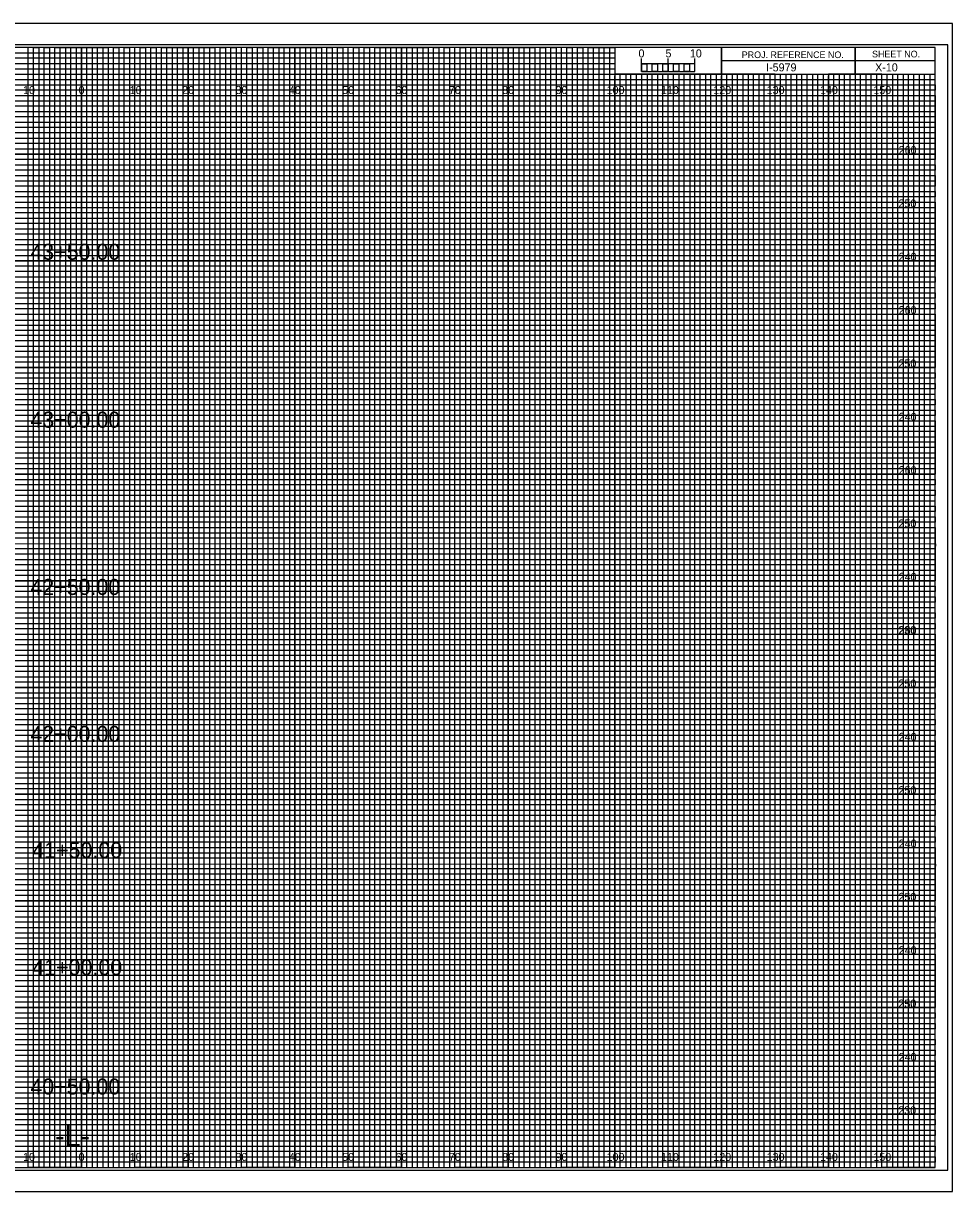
# Model space of a CAD drawing. Extents: x -13 to 359, y -5 to 2854.
# Drawn here: x 149.1 to 323.3, y 1975.5 to 2194.5 of the extents above; entities that cross this region are included whole.
import ezdxf

# ---------------------------------------------------------------- set-up
doc = ezdxf.new("R2010")
doc.units = 0
for name, color, linetype in [('Exist CMT Pavement', 7, 'Continuous'), ('Exist Cross Section Cell', 7, 'Continuous'), ('Exist XS Ground Line', 7, 'Continuous'), ('Prop CMT Conc Surface', 7, 'Continuous'), ('Prop CMT Concrete Structures', 7, 'Continuous'), ('Prop CMT DNC', 7, 'Continuous'), ('Prop CMT Pvmt Course 1', 7, 'Continuous'), ('Prop CMT Pvmt Course 1 CG', 7, 'Continuous'), ('Prop CMT Pvmt Course 1 Wedge', 7, 'Continuous'), ('Prop CMT Pvmt Course 2', 7, 'Continuous'), ('Prop CMT Pvmt Course 2 Wedge', 7, 'Continuous'), ('Prop CMT Pvmt Course 3', 7, 'Continuous'), ('Prop CMT Pvmt Course 3 Wedge', 7, 'Continuous'), ('Prop CMT Shear Line', 7, 'Continuous'), ('Prop CMT Slope Grass', 7, 'Continuous'), ('Prop CMT Subgrade Earthwork', 7, 'Continuous'), ('Scratch_Level_0', 7, 'Continuous')]:
    doc.layers.add(name, color=color, linetype=linetype)

msp = doc.modelspace()

# ---------------------------------------------------------------- linework, layer by layer
at = {"layer": 'Exist XS Ground Line'}
for p, q in [((150, 2190), (140, 2190)), ((150, 1980), (150, 2190)), ((170, 2190), (160, 2190)), ((160, 2190), (160, 1980)), ((170, 1980), (170, 2190)), ((190, 2190), (180, 2190)), ((180, 2190), (180, 1980)), ((190, 1980), (190, 2190)), ((210, 2190), (200, 2190)), ((200, 2190), (200, 1980)), ((210, 1980), (210, 2190)), ((230, 2190), (220, 2190)), ((220, 2190), (220, 1980)), ((230, 1980), (230, 2190)), ((250, 2190), (240, 2190)), ((240, 2190), (240, 1980)), ((250, 1980), (250, 2190)), ((260, 2190), (260, 1980)), ((270, 1980), (270, 2185)), ((290, 2185), (280, 2185)), ((280, 2185), (280, 1980)), ((290, 1980), (290, 2185)), ((310, 2185), (300, 2185)), ((300, 2185), (300, 1980)), ((310, 1980), (310, 2185)), ((160, 1980), (150, 1980)), ((180, 1980), (170, 1980)), ((200, 1980), (190, 1980)), ((220, 1980), (210, 1980)), ((240, 1980), (230, 1980)), ((260, 1980), (250, 1980)), ((280, 1980), (270, 1980)), ((300, 1980), (290, 1980)), ((320, 1980), (310, 1980)), ((320, 1980), (320, 1980))]:
    msp.add_line(p, q, dxfattribs=at)
for points in [[(0, 2180), (320, 2180), (320, 2170), (0, 2170)], [(0, 2160), (320, 2160), (320, 2150), (0, 2150)], [(0, 2140), (320, 2140), (320, 2130), (0, 2130)], [(0, 2120), (320, 2120), (320, 2110), (0, 2110)], [(0, 2100), (320, 2100), (320, 2090), (0, 2090)], [(0, 2080), (320, 2080), (320, 2070), (0, 2070)], [(0, 2060), (320, 2060), (320, 2050), (0, 2050)], [(0, 2040), (320, 2040), (320, 2030), (0, 2030)], [(0, 2020), (320, 2020), (320, 2010), (0, 2010)], [(0, 2000), (320, 2000), (320, 1990), (0, 1990)]]:
    msp.add_lwpolyline(points, dxfattribs=at)
at = {"layer": 'Prop CMT Conc Surface'}
for p, q in [((265, 2185.49), (265, 2187.9)), ((265, 2186.9), (265, 2187.9)), ((270, 2185.49), (270, 2187.9)), ((275, 2185.49), (275, 2187.9)), ((275, 2186.9), (275, 2187.9))]:
    msp.add_line(p, q, dxfattribs=at)
for points in [[(275, 2186.9), (265, 2186.9), (265, 2185.49), (275, 2185.49)], [(265, 2186.9), (266, 2186.9), (266, 2185.49), (265, 2185.49)], [(267, 2186.9), (268, 2186.9), (268, 2185.49), (267, 2185.49)], [(269, 2186.9), (270, 2186.9), (270, 2185.49), (269, 2185.49)], [(271, 2186.9), (272, 2186.9), (272, 2185.49), (271, 2185.49)], [(273, 2186.9), (274, 2186.9), (274, 2185.49), (273, 2185.49)]]:
    msp.add_lwpolyline(points, close=True, dxfattribs=at)
at = {"layer": 'Prop CMT Concrete Structures'}
for p, q in [((305, 2190), (305, 2185)), ((305, 2185), (305, 2190)), ((280, 2187.5), (280, 2185)), ((320, 2187.49), (280, 2187.49)), ((280, 2185), (320, 2185))]:
    msp.add_line(p, q, dxfattribs=at)
for points in [[(320, 2190), (0, 2190), (0, 1980), (320, 1980)], [(280, 2190), (260, 2190), (260, 2185.03), (280, 2185.03)], [(320, 2190), (280, 2190), (280, 2185), (320, 2185)]]:
    msp.add_lwpolyline(points, close=True, dxfattribs=at)
at = {"layer": 'Prop CMT DNC'}
for p, q in [((323.3, 2194.5), (-13.4, 2194.5)), ((-13.4, 1975.5), (323.3, 1975.5))]:
    msp.add_line(p, q, dxfattribs=at)
at = {"layer": 'Prop CMT Pvmt Course 1'}
for p, q in [((0, 2189), (260, 2189)), ((260, 2187.98), (0, 2187.98)), ((260, 2189), (260, 2187.98)), ((0, 2187), (260, 2187)), ((260, 2185.89), (0, 2185.89)), ((260, 2187), (260, 2185.89)), ((0, 2184), (320, 2184))]:
    msp.add_line(p, q, dxfattribs=at)
for points in [[(0, 2183), (270, 2183), (320, 2183), (320, 2182), (0, 2182)], [(0, 2181), (320, 2181), (320, 2179), (0, 2179)], [(0, 2178), (320, 2178), (320, 2177), (0, 2176.98)], [(0, 2176), (320, 2176), (320, 2174), (0, 2174)], [(0, 2173), (320, 2173), (320, 2172), (0, 2172)], [(0, 2171), (320, 2171), (320, 2169), (0, 2169)], [(0, 2168), (320, 2168), (320, 2167), (0, 2167)], [(0, 2166), (320, 2166), (320, 2164), (0, 2164)], [(0, 2163), (320, 2163), (320, 2162), (0, 2162)], [(0, 2161), (320, 2161), (320, 2159), (0, 2159)], [(0, 2158), (320, 2158), (320, 2157), (0, 2157)], [(0, 2156), (320, 2156), (320, 2153.95), (320, 2153), (320, 2152), (0, 2152)], [(0, 2154), (320, 2154), (320, 2153), (0, 2153)], [(0, 2151), (320, 2151), (320, 2149), (0, 2149.03)], [(0, 2149.03), (320, 2149), (320, 2148), (0, 2148)], [(0, 2147), (320, 2147), (320, 2146), (0, 2146)], [(0, 2144), (320, 2144), (320, 2143), (0, 2143)], [(0, 2142), (320, 2142), (320, 2141), (0, 2141)], [(-0.07, 2138.89), (320, 2138.89), (320, 2137.88), (-0.07, 2137.88)], [(0, 2137), (320, 2137), (320, 2136), (0, 2136)], [(0, 2134), (320, 2134), (320, 2133), (0, 2133)], [(0, 2132), (320, 2132), (320, 2131), (0, 2131)], [(0, 2129), (320, 2129), (320, 2128), (0, 2128)], [(0, 2127), (320, 2127), (320, 2126), (0, 2126)], [(0, 2124), (320, 2124), (320, 2123), (0, 2123)], [(0, 2122), (320, 2122), (320, 2121), (0, 2121)], [(0, 2119), (320, 2119), (319.99, 2117.98), (0, 2118)], [(0, 2117), (320, 2117), (320, 2116), (0, 2116)], [(0, 2114), (320, 2114), (320, 2113), (0, 2113)], [(0, 2112), (320, 2112), (320, 2111), (0, 2111)], [(0, 2109), (320, 2109), (320, 2108), (0, 2108)], [(0, 2107), (320, 2107), (320, 2106), (0, 2106)], [(0, 2104), (320, 2104), (320, 2103), (0, 2103)], [(0, 2102), (320, 2102), (320, 2101), (0, 2101)], [(0, 2099), (320, 2099), (320, 2098), (0, 2098)], [(0, 2096.99), (320.07, 2096.91), (320, 2096), (0, 2096)], [(0, 2094), (320, 2094), (320, 2093), (0, 2093)], [(0, 2092), (320, 2092), (320, 2091), (0, 2091)], [(0, 2089), (320, 2089), (320, 2088), (0, 2088)], [(0, 2087), (320, 2087), (320, 2086), (0, 2086)], [(0, 2084), (320, 2084), (320, 2083), (0, 2083)], [(0, 2082), (320, 2082), (320, 2081), (0, 2081)], [(0, 2079), (320, 2079), (320, 2078), (0, 2078)], [(0, 2077), (320, 2077), (320, 2076), (0, 2076)], [(0, 2074), (320, 2074), (320, 2073), (0, 2073)], [(0, 2072), (320, 2072), (320, 2071), (0, 2071)], [(0, 2069), (320, 2069), (320, 2068), (0, 2068)], [(0, 2067), (320, 2067), (320, 2066), (0, 2066)], [(0, 2064), (320, 2064), (320, 2063), (0, 2063)], [(0, 2062), (320, 2062), (320, 2061), (0, 2061)], [(0, 2059), (320, 2059), (319.99, 2057.98), (0, 2058)], [(0, 2057), (320, 2057), (320, 2056), (0, 2056)], [(0, 2054), (320, 2054), (320, 2053), (0, 2053)], [(0, 2052), (320, 2052), (320, 2051), (0, 2051)], [(0, 2049), (320, 2049), (320, 2048), (0, 2048)], [(0, 2047), (320, 2047), (320, 2046), (0, 2046)], [(0, 2044), (320, 2044), (320, 2043), (0, 2043)], [(0, 2042), (320, 2042), (320, 2041), (0, 2041)], [(0, 2039), (320, 2039), (320, 2038), (0, 2038)], [(0, 2036.99), (320.07, 2036.91), (320, 2036), (0, 2036)], [(0, 2034), (320, 2034), (320, 2033), (0, 2033)], [(0, 2032), (320, 2032), (320, 2031), (0, 2031)], [(0, 2029), (320, 2029), (320, 2028), (0, 2028)], [(0, 2027), (320, 2027), (320, 2026), (0, 2026)], [(0, 2024), (320, 2024), (320, 2023), (0, 2023)], [(0, 2022), (320, 2022), (320, 2021), (0, 2021)], [(0, 2019), (320, 2019), (320, 2018), (0, 2018)], [(0, 2017), (320, 2017), (320, 2016), (0, 2016)], [(0, 2014), (320, 2014), (320, 2013), (0, 2013)], [(0, 2012), (320, 2012), (320, 2011), (0, 2011)], [(0, 2009), (320, 2009), (320, 2008), (0, 2008)], [(0, 2007), (320, 2007), (320, 2006), (0, 2006)], [(0, 2004), (320, 2004), (320, 2003), (0, 2003)], [(0, 2002), (320, 2002), (320, 2001), (0, 2001)], [(0, 1999), (320, 1999), (320, 1998), (0, 1998)], [(0, 1997), (320, 1997), (320, 1996), (0, 1996)], [(0, 1994), (320, 1994), (320, 1993), (0, 1993)], [(0, 1992), (320, 1992), (320, 1991), (0, 1991)], [(0, 1989), (320, 1989), (320, 1988), (0, 1988)], [(0, 1987), (320, 1987), (320, 1986), (0, 1986)], [(0, 1984), (320, 1984), (320, 1983), (0, 1983)], [(0, 1982), (320, 1982), (320, 1981), (0, 1981)]]:
    msp.add_lwpolyline(points, dxfattribs=at)
at = {"layer": 'Prop CMT Pvmt Course 1 CG'}
for p, q in [((267, 2185), (266.01, 2185)), ((266.01, 2185), (266.01, 1980)), ((267, 1980), (267, 2185)), ((269, 2185), (268, 2185)), ((268, 2185), (268, 1980)), ((269, 1980), (269, 2185)), ((266.01, 1980), (265, 1980)), ((268, 1980), (267, 1980))]:
    msp.add_line(p, q, dxfattribs=at)
for points in [[(150, 1980), (151, 1980), (151, 2190), (152, 2190), (152, 1980)], [(152, 1980), (153, 1980), (153, 2190), (154, 2190), (154, 1980)], [(155, 1980), (156, 1980), (156, 2190), (157, 2190), (157, 1980)], [(157, 1980), (158, 1980), (158, 2190), (159, 2190), (159, 1980)], [(160, 1980), (161, 1980), (161, 2190), (162, 2190), (162, 1980)], [(162, 1980), (163, 1980), (163, 2190), (164, 2190), (164, 1980)], [(165, 1980), (166, 1980), (166, 2190), (167, 2190), (167, 1980)], [(167, 1980), (168, 1980), (168, 2190), (169, 2190), (169, 1980)], [(170, 1980), (171, 1980), (171, 2190), (172, 2190), (172, 1980)], [(172, 1980), (173, 1980), (173, 2190), (174, 2190), (174, 1980)], [(175, 1980), (176, 1980), (176, 2190), (177, 2190), (177, 1980)], [(177, 1980), (178, 1980), (178, 2190), (179, 2190), (179, 1980)], [(180, 1980), (181, 1980), (181, 2190), (182, 2190), (182, 1980)], [(182, 1980), (183, 1980), (183, 2190), (184, 2190), (184, 1980)], [(185, 1980), (186, 1980), (186, 2190), (187, 2190), (187, 1980)], [(187, 1980), (188, 1980), (188, 2190), (189, 2190), (189, 1980)], [(190, 1980), (191, 1980), (191, 2190), (192, 2190), (192, 1980)], [(192, 1980), (193, 1980), (193, 2190), (194, 2190), (194, 1980)], [(195, 1980), (196, 1980), (196, 2190), (197, 2190), (197, 1980)], [(197, 1980), (198, 1980), (198, 2190), (199, 2190), (199, 1980)], [(200, 1980), (201, 1980), (201, 2190), (202, 2190), (202, 1980)], [(202, 1980), (203, 1980), (203, 2190), (204, 2190), (204, 1980)], [(205, 1980), (206, 1980), (206, 2190), (207, 2190), (207, 1980)], [(207, 1980), (208, 1980), (208, 2190), (209, 2190), (209, 1980)], [(210, 1980), (211, 1980), (211, 2190), (212, 2190), (212, 1980)], [(212, 1980), (213, 1980), (213, 2190), (214, 2190), (214, 1980)], [(215, 1980), (216, 1980), (216, 2190), (217, 2190), (217, 1980)], [(217, 1980), (218, 1980), (218, 2190), (219, 2190), (219, 1980)], [(220, 1980), (221, 1980), (221, 2190), (222, 2190), (222, 1980)], [(222, 1980), (223, 1980), (223, 2190), (224, 2190), (224, 1980)], [(225, 1980), (226, 1980), (226, 2190), (227, 2190), (227, 1980)], [(227, 1980), (228, 1980), (228, 2190), (229, 2190), (229, 1980)], [(230, 1980), (231, 1980), (231, 2190), (232, 2190), (232, 1980)], [(232, 1980), (233, 1980), (233, 2190), (234, 2190), (234, 1980)], [(235, 1980), (236, 1980), (236, 2190), (237, 2190), (237, 1980)], [(237, 1980), (238, 1980), (238, 2190), (239, 2190), (239, 1980)], [(240, 1980), (241, 1980), (241, 2190), (242, 2190), (242, 1980)], [(242, 1980), (243, 1980), (243, 2190), (244, 2190), (244, 1980)], [(245, 1980), (246, 1980), (246, 2190), (247, 2190), (247, 1980)], [(247, 1980), (248, 1980), (248, 2190), (249, 2190), (249, 1980)], [(250, 1980), (251, 1980), (251, 2190), (252, 2190), (252, 1980)], [(252, 1980), (253, 1980), (253, 2190), (254, 2190), (254, 1980)], [(255, 1980), (256, 1980), (256, 2190), (257, 2190), (257, 1980)], [(257, 1980), (258, 1980), (258, 2190), (259, 2190), (259, 1980)], [(260, 1980), (261, 1980), (261, 2185), (262.02, 2185), (262.02, 1980)], [(262, 1980), (263, 1980), (263, 2185), (263.99, 2185), (263.99, 1980)], [(270, 1980), (270.98, 1980), (270.98, 2185), (272, 2185), (272, 1980)], [(272, 1980), (273, 1980), (273, 2185), (274.05, 2185), (274.05, 1980)], [(275, 1980), (276, 1980), (276, 2185), (277, 2185), (277, 1980)], [(277, 1980), (278, 1980), (278, 2185), (279, 2185), (279, 1980)], [(280, 1980), (281, 1980), (281, 2185), (282, 2185), (282, 1980)], [(282, 1980), (283, 1980), (283, 2185), (284, 2185), (284, 1980)], [(285, 1980), (286, 1980), (286, 2185), (287, 2185), (287, 1980)], [(287, 1980), (288, 1980), (288, 2185), (289, 2185), (289, 1980)], [(290, 1980), (291, 1980), (291, 2185), (292, 2185), (292, 1980)], [(292, 1980), (293, 1980), (293, 2185), (294, 2185), (294, 1980)], [(295, 1980), (296, 1980), (296, 2185), (297, 2185), (297, 1980)], [(297, 1980), (298, 1980), (298, 2185), (299, 2185), (299, 1980)], [(300, 1980), (301, 1980), (301, 2185), (302, 2185), (302, 1980)], [(302, 1980), (303, 1980), (303, 2185), (304, 2185), (304, 1980)], [(305, 1980), (306, 1980), (306, 2185), (307, 2185), (307, 1980)], [(307, 1980), (308, 1980), (308, 2185), (309, 2185), (309, 1980)], [(310, 1980), (311, 1980), (311, 2185), (312, 2185), (312, 1980)], [(312, 1980), (313, 1980), (313, 2185), (314, 2185), (314, 1980)], [(315, 1980), (316, 1980), (316, 2185), (317, 2185), (317, 1980)], [(317, 1980), (318, 1980), (318, 2185), (319, 2185), (319, 1980)]]:
    msp.add_lwpolyline(points, dxfattribs=at)
at = {"layer": 'Prop CMT Shear Line'}
for p, q in [((150, 1980), (150, 2190)), ((160, 1980), (160, 2190)), ((170, 1980), (170, 2190)), ((180, 1980), (180, 2190)), ((190, 1980), (190, 2190)), ((200, 1980), (200, 2190)), ((210, 1980), (210, 2190)), ((220, 1980), (220, 2190)), ((230, 1980), (230, 2190)), ((240, 1980), (240, 2190)), ((250, 1980), (250, 2190)), ((260, 1980), (260, 2184.69)), ((270, 1980), (270, 2184.69)), ((280, 1980), (280, 2184.69)), ((290, 1980), (290, 2184.69)), ((300, 1980), (300, 2184.69)), ((310, 1980), (310, 2184.69)), ((0, 2180), (320, 2180)), ((0, 2170), (320, 2170)), ((0, 2160), (320, 2160)), ((0, 2150), (320, 2150)), ((0, 2140), (320, 2140)), ((0, 2130), (320, 2130)), ((0, 2120), (320, 2120)), ((0, 2110), (320, 2110)), ((0, 2100), (320, 2100)), ((0, 2090), (320, 2090)), ((0, 2080), (320, 2080)), ((0, 2070), (320, 2070)), ((0, 2060), (320, 2060)), ((0, 2050), (320, 2050)), ((0, 2040), (320, 2040)), ((0, 2030), (320, 2030)), ((0, 2020), (320, 2020)), ((0, 2010), (320, 2010)), ((0, 2000), (320, 2000)), ((0, 1990), (320, 1990))]:
    msp.add_line(p, q, dxfattribs=at)
at = {"layer": 'Prop CMT Slope Grass'}
msp.add_lwpolyline([(-10.8, 1979.5), (322.4, 1979.5), (322.4, 2190.5), (-10.8, 2190.5)], close=True, dxfattribs=at)
at = {"layer": 'Prop CMT Subgrade Earthwork'}
msp.add_lwpolyline([(-13.4, 1975.5), (323.3, 1975.5), (323.3, 2194.5), (-13.4, 2194.5)], close=True, dxfattribs=at)
at = {"layer": 'Scratch_Level_0'}
for points in [[(145, 1980), (155, 1980), (155, 2190), (165, 2190), (165, 1980), (175, 1980), (175, 2190), (185, 2190), (185, 1980), (195, 1980), (195, 2190), (205, 2190), (205, 1980), (215, 1980), (215, 2190), (225, 2190), (225, 1980), (235, 1980), (235, 2190), (245, 2190), (245, 1980), (255, 1980), (255, 2190), (259.93, 2190), (260, 2190), (260, 2185), (264.99, 2185), (264.99, 1980), (275, 1980), (275, 2185), (285, 2185), (285, 1980), (295, 1980), (295, 2185), (305, 2185), (305, 1980), (315, 1980), (315, 2185)], [(0, 2185), (275, 2185)], [(0, 2165), (320, 2165), (320, 2175), (0, 2175)], [(0, 2145), (320, 2145), (320, 2155), (0, 2155)], [(0, 2125), (320, 2125), (320, 2135), (0, 2135)], [(0, 2105), (320, 2105), (320, 2115), (0, 2115)], [(0, 2085), (320, 2085), (320, 2095), (0, 2095)], [(0, 2065), (320, 2065), (320, 2075), (0, 2075)], [(0, 2045), (320, 2045), (320, 2055), (0, 2055)], [(0, 2025), (320, 2025), (320, 2035), (0, 2035)], [(0, 2005), (320, 2005), (320, 2015), (0, 2015)], [(0, 1985), (320, 1985), (320, 1995), (0, 1995)]]:
    msp.add_lwpolyline(points, dxfattribs=at)

# ---------------------------------------------------------------- texts
at = {"layer": 'Exist CMT Pavement'}
for s, p in [('5', (269.47, 2188.12)), ('10', (274.04, 2188.12))]:
    msp.add_text(s, height=1.5, dxfattribs=at).set_placement(p)
at = {"layer": 'Exist Cross Section Cell'}
for s, p in [('10', (149.04, 2181.25)), ('0', (159.45, 2181.25)), ('0', (159.45, 2181.25)), ('10', (169.04, 2181.25)), ('20', (178.86, 2181.25)), ('30', (188.86, 2181.25)), ('40', (198.86, 2181.25)), ('50', (208.86, 2181.25)), ('60', (218.86, 2181.25)), ('70', (228.86, 2181.25)), ('80', (238.86, 2181.25)), ('90', (248.86, 2181.25)), ('100', (258.44, 2181.25)), ('110', (268.62, 2181.25)), ('120', (278.44, 2181.25)), ('130', (288.44, 2181.25)), ('140', (298.44, 2181.25)), ('150', (308.44, 2181.25)), ('10', (149.04, 1981.25)), ('0', (159.45, 1981.25)), ('0', (159.45, 1981.25)), ('10', (169.04, 1981.25)), ('20', (178.86, 1981.25)), ('30', (188.86, 1981.25)), ('40', (198.86, 1981.25)), ('50', (208.86, 1981.25)), ('60', (218.86, 1981.25)), ('70', (228.86, 1981.25)), ('80', (238.86, 1981.25)), ('90', (248.86, 1981.25)), ('100', (258.44, 1981.25)), ('110', (268.62, 1981.25)), ('120', (278.44, 1981.25)), ('130', (288.44, 1981.25)), ('140', (298.44, 1981.25)), ('150', (308.44, 1981.25))]:
    msp.add_text(s, height=1.5, dxfattribs=at).set_placement(p)
at = {"layer": 'Prop CMT Conc Surface'}
msp.add_text('0', height=1.5, dxfattribs=at).set_placement((264.41, 2188.12))
at = {"layer": 'Prop CMT Concrete Structures'}
for s, p in [('PROJ. REFERENCE NO.', (283.77, 2187.99)), ('SHEET NO.', (308.19, 2188.12))]:
    msp.add_text(s, height=1.25, dxfattribs=at).set_placement(p)
at = {"layer": 'Prop CMT Pvmt Course 1 Wedge'}
msp.add_text('X-10', height=1.5, dxfattribs=at).set_placement((308.77, 2185.5))
at = {"layer": 'Prop CMT Pvmt Course 2'}
for s, p in [('260', (313.19, 2170)), ('250', (313.15, 2160)), ('240', (313.19, 2150)), ('260', (313.19, 2140)), ('250', (313.15, 2130)), ('240', (313.19, 2120)), ('260', (313.19, 2110)), ('250', (313.15, 2100)), ('240', (313.19, 2090)), ('230', (313.11, 2080)), ('260', (313.19, 2080)), ('250', (313.15, 2070)), ('240', (313.19, 2060)), ('250', (313.15, 2050)), ('240', (313.19, 2040)), ('250', (313.15, 2030)), ('240', (313.19, 2020)), ('230', (313.11, 2010)), ('250', (313.15, 2010)), ('240', (313.19, 2000)), ('230', (313.11, 1990))]:
    msp.add_text(s, height=1.5, dxfattribs=at).set_placement(p)
at = {"layer": 'Prop CMT Pvmt Course 2 Wedge'}
msp.add_text('I-5979', height=1.5, dxfattribs=at).set_placement((288.34, 2185.5))
at = {"layer": 'Prop CMT Pvmt Course 3'}
for s, p in [('43+50.00', (150.41, 2150.19)), ('43+00.00', (150.41, 2118.71)), ('42+50.00', (150.41, 2087.35)), ('42+00.00', (150.41, 2059.81)), ('41+50.00', (150.77, 2038.02)), ('41+00.00', (150.77, 2016.06)), ('40+50.00', (150.41, 1993.7))]:
    msp.add_text(s, height=3, dxfattribs=at).set_placement(p)
at = {"layer": 'Prop CMT Pvmt Course 3 Wedge'}
msp.add_text('-L-', height=4, dxfattribs=at).set_placement((155.06, 1984))

doc.saveas('drawing.dxf')
